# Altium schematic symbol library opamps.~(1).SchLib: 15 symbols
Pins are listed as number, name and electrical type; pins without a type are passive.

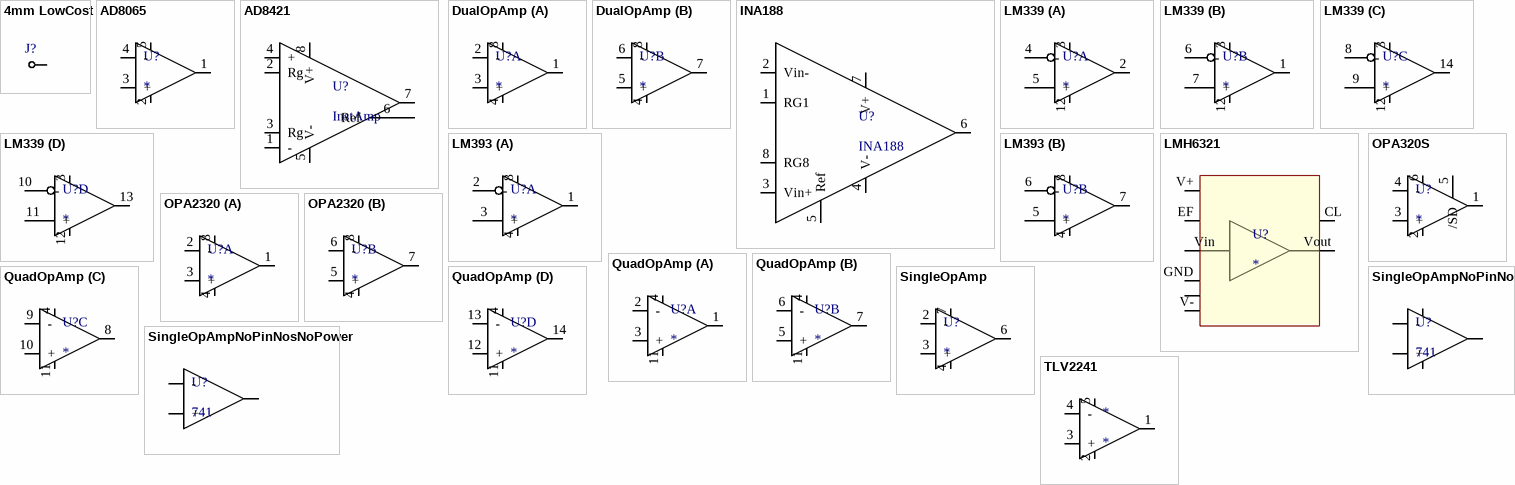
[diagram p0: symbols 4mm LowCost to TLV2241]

## 4mm LowCost
designator J?  (value not drawn)
footprint 4mm Socket Lo cost (Low cost 4mm socket)
pins: 1

## AD8065
designator U?
footprint SOT23-5 (% pin SOT 23 with longish pads)
pins: 1 OP, 2 V-, 3 +, 4 -, 5 V+

## AD8421
designator U?, comment InstAmp
footprint SOIC 8
pins: 1 -, 2 Rg, 3 Rg, 4 +, 5 V-, 6 Ref, 7 Out, 8 V+

## DualOpAmp
designator U?
footprint SOIC 8
part A pins: 1 OP, 2 -, 3 +, 4 V-, 8 V+
part B pins: 4 V-, 5 +, 6 -, 7 OP, 8 V+

## INA188
designator U?
footprint SOIC 8
pins: 1 RG1, 2 Vin-, 3 Vin+, 4 V-, 5 Ref, 6 Vout, 7 V+, 8 RG8

## LM339
designator U?
footprint SOIC 14
part A pins: 2 OP, 3 V+, 4 -, 5 +, 12 V-
part B pins: 1 OP, 3 V+, 6 -, 7 +, 12 V-
part C pins: 3 V+, 8 -, 9 +, 12 V-, 14 OP
part D pins: 3 V+, 10 -, 11 +, 12 V-, 13 OP

## LM393
designator U?
footprint SOIC 8
part A pins: 1 OP, 2 -, 3 +, 4 V-, 8 V+
part B pins: 4 V-, 5 +, 6 -, 7 OP, 8 V+

## LMH6321
designator U?
footprint TI KTW; pin to pad CL>7 EF>6 GND>2 PAD>8 V+>5 V->4 Vin>1 Vout>3
pins: CL, EF, GND, PAD, V+, V-, Vin, Vout

## OPA320S
designator U?
footprint SOT23-6 (6 pin SOT 23 with longish pads)
pins: 1 OP, 2 V-, 3 +, 4 -, 5 /SD, 6 V+

## OPA2320
designator U?
part A pins: 1 OP, 2 -, 3 +, 4 V-, 8 V+
part B pins: 4 V-, 5 +, 6 -, 7 OP, 8 V+

## QuadOpAmp
designator U?
footprint SOIC 14
part A pins: 1 OP, 2 -, 3 +, 4 V+, 11 V-
part B pins: 4 V+, 5 +, 6 -, 7 OP, 11 V-
part C pins: 4 V+, 8 OP, 9 -, 10 +, 11 V-
part D pins: 4 V+, 11 V-, 12 +, 13 -, 14 OP

## SingleOpAmp
designator U?
footprint SOIC 8
pins: 2 -, 3 +, 4 V-, 6 OP, 7 V+

## SingleOpAmpNoPinNos
designator U?, comment 741
footprint SOIC 8
pins: 2 -, 3 +, 4 V-, 6 OP, 7 V+

## SingleOpAmpNoPinNosNoPower
designator U?, comment 741
footprint SOIC 8
pins: 2 -, 3 +, 6 OP

## TLV2241
designator *
footprint SOT23-5 (% pin SOT 23 with longish pads)
pins: 1 OP, 2 Gnd, 3 +, 4 -, 5 V+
